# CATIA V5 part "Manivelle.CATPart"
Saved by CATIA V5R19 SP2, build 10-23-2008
Part number: Manivelle
Publications: "Dav", "Dmc", "Emanivelle"
Bounding box of the stored display mesh (mm): x 0 to 20, y -14.999 to 14.999, z -108 to 14.99
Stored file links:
  C:\Users\Vianney\Documents\Garantie\Cours\2A\IAO\IAO-proj-Catia\Manivelle.CATPart
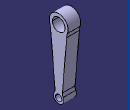
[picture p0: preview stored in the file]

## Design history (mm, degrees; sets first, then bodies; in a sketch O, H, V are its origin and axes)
Parameters
  Dav = 20 mm
  Dmc = 10 mm
  Emanivelle = 100 mm
Body1 (main body)
  Sketch1 on yz-plane, origin (0, 0, 0), H (0, 1, 0), V (0, 0, 1)
    circle A1 centre (0, 0) radius 10
    circle A2 centre (0, -100) radius 5
    point P1 (0, -100)
    arc A3 centre (0, 0) radius 15 from (13.0322, -7.4272) to (-13.0322, -7.4272) ccw
    arc A4 centre (0, -100) radius 8 from (-5.5199, -94.2095) to (5.5199, -94.2095) ccw
    point P2 (-15, 0)
    line L1 (-13.0322, -7.4272) -> (-5.5199, -94.2095)
    point P3 (-13.0322, -7.4272)
    point P4 (-5.5199, -94.2095)
    point P5 (5.5199, -94.2095)
    point P6 (13.0322, -7.4272)
    line L2 (13.0322, -7.4272) -> (5.5199, -94.2095)
    radius A1 = 10 {= Dav /2}
    radius A2 = 5 {= Dmc/2}
    distance P1 O = 100 {= Emanivelle}
    radius A3 = 15 {= Dav /2+5mm}
    radius A4 = 8 {= Dmc /2+3mm}
    coincidence: P1 V, P2 A3, P2 H
    tangency: L1 A2
    symmetry: P4 P5 V, P3 P6 V, L1 L2 V
  Pad1: profile Sketch1, direction (1, 0, 0), length 20
  Fillet1: radius 10, on edge [face of Pad1 from Sketch1.A4 | face of Pad1 from Sketch1.L1]; edge [face of Pad1 from Sketch1.L2 | face of Pad1 from Sketch1.A4]
  Fillet2: radius 25, on edge [face of Pad1 from Sketch1.L1 | face of Pad1 from Sketch1.A3]; edge [face of Pad1 from Sketch1.A3 | face of Pad1 from Sketch1.L2]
